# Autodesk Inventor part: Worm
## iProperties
Created: 2008-01
Part Number: Worm
Material: Steel, Mild
Document SubType Name: Modeling
Designer: eruiz-tagle
Mass: 6.17747 g
Surface Area: 13.4788 cm^2
Volume: 0.785938 cm^3
Density: 7.86 g/cm^3
CustomPartVersion: 1
Author: eruiz-tagle
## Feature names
1. Base Body [Extrusion]
2. Chamfer1
3. Chamfer2
4. Tooth
5. Tooth Pattern [Circular Pattern]
6. Left Tooth
7. Left Tooth Pattern [Circular Pattern]
